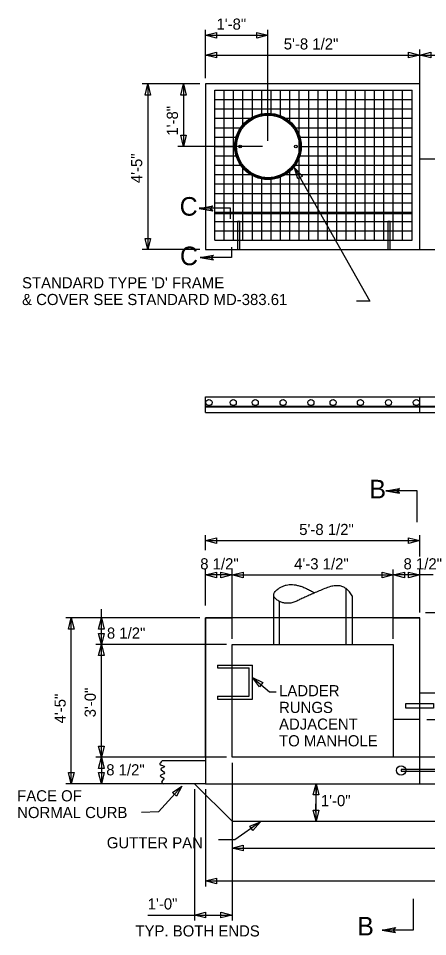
# Model space of a CAD drawing. Extents: x 100.2 to 136.1, y 126.8 to 178.4.
# Drawn here: x 101.15 to 112.05, y 153.91 to 178.38 of the extents above; entities that cross this region are included whole.
import ezdxf

# ---------------------------------------------------------------- set-up
doc = ezdxf.new("R2010")
doc.units = 0
for name, color, linetype in [('DETL-DIMS', 7, 'Continuous'), ('DETL-LINE', 7, 'Continuous'), ('DETL-NOTE', 7, 'Continuous')]:
    doc.layers.add(name, color=color, linetype=linetype)

msp = doc.modelspace()

# ---------------------------------------------------------------- linework, layer by layer
at = {"layer": 'DETL-DIMS'}
for p, q in [((106.133, 176.78), (106.133, 178.076)), ((106.133, 177.928), (107.799, 177.928)), ((107.799, 175.114), (107.799, 178.076)), ((106.133, 176.78), (106.133, 177.548)), ((111.841, 176.78), (111.841, 177.548)), ((111.841, 174.78), (111.841, 177.548)), ((106.133, 177.4), (111.841, 177.4)), ((111.841, 177.4), (116.841, 177.4)), ((105.985, 176.632), (104.451, 176.632)), ((104.599, 176.632), (104.599, 172.215)), ((105.985, 176.632), (105.402, 176.632)), ((105.55, 176.632), (105.55, 174.966)), ((107.651, 174.966), (105.402, 174.966)), ((105.968, 173.315), (106.326, 173.378)), ((105.968, 173.315), (106.326, 173.253)), ((106.258, 173.315), (106.326, 173.378)), ((106.326, 173.253), (106.258, 173.315)), ((105.985, 172.215), (104.451, 172.215)), ((105.994, 172.003), (106.352, 172.066)), ((106.284, 172.003), (106.352, 172.066)), ((105.994, 172.003), (106.352, 171.941)), ((106.352, 171.941), (106.284, 172.003)), ((110.939, 165.789), (111.297, 165.852)), ((110.939, 165.789), (111.297, 165.727)), ((111.229, 165.789), (111.297, 165.852)), ((111.297, 165.727), (111.229, 165.789)), ((106.133, 164.207), (106.133, 164.61)), ((106.133, 164.462), (111.841, 164.462)), ((111.841, 164.041), (111.841, 164.61)), ((106.133, 162.728), (106.133, 163.694)), ((106.841, 163.546), (106.133, 163.546)), ((106.781, 163.546), (106.841, 163.546)), ((106.841, 161.841), (106.841, 163.694)), ((106.841, 161.841), (106.841, 163.694)), ((106.841, 163.546), (111.133, 163.546)), ((111.133, 161.841), (111.133, 163.694)), ((111.133, 161.841), (111.133, 163.694)), ((111.841, 163.546), (111.133, 163.546)), ((111.841, 162.549), (111.841, 163.694)), ((112.193, 163.546), (111.841, 163.546)), ((103.362, 161.693), (103.362, 162.635)), ((111.989, 162.549), (113.451, 162.549)), ((105.985, 162.401), (102.413, 162.401)), ((102.561, 157.984), (102.561, 162.401)), ((105.985, 162.401), (103.214, 162.401)), ((106.693, 161.693), (103.214, 161.693)), ((106.693, 161.693), (103.214, 161.693)), ((103.362, 158.688), (103.362, 161.693)), ((111.989, 160.401), (113.451, 160.401)), ((106.693, 158.688), (103.214, 158.688)), ((106.693, 158.688), (103.214, 158.688)), ((103.362, 158.674), (103.362, 157.984)), ((106.841, 158.54), (106.841, 156.121)), ((104.865, 157.984), (102.413, 157.984)), ((105.985, 157.984), (103.214, 157.984)), ((105.841, 157.836), (105.841, 154.336)), ((106.133, 157.836), (106.133, 155.243)), ((109.078, 157.984), (109.077, 157.445)), ((109.078, 156.984), (109.078, 157.984)), ((109.078, 156.984), (109.077, 157.445)), ((106.841, 156.836), (106.841, 154.336)), ((106.841, 156.269), (126.841, 156.269)), ((106.133, 155.391), (127.549, 155.391)), ((104.597, 154.484), (105.841, 154.484)), ((105.841, 154.484), (106.841, 154.484)), ((110.837, 154.084), (111.195, 154.147)), ((110.837, 154.084), (111.195, 154.022)), ((111.127, 154.084), (111.195, 154.147)), ((111.195, 154.022), (111.127, 154.084))]:
    msp.add_line(p, q, dxfattribs=at)
for points in [[(106.43, 177.854), (106.133, 177.928), (106.43, 178.002)], [(107.502, 178.002), (107.799, 177.928), (107.502, 177.854)], [(106.43, 177.326), (106.133, 177.4), (106.43, 177.474)], [(111.544, 177.474), (111.841, 177.4), (111.544, 177.326)], [(112.138, 177.326), (111.841, 177.4), (112.138, 177.474)], [(104.525, 176.335), (104.599, 176.632), (104.673, 176.335)], [(105.476, 176.335), (105.55, 176.632), (105.624, 176.335)], [(105.624, 175.263), (105.55, 174.966), (105.476, 175.263)], [(108.59, 174.104), (108.509, 174.399), (108.719, 174.176)], [(106.326, 173.253), (105.968, 173.315), (106.326, 173.378), (106.258, 173.315)], [(104.673, 172.512), (104.599, 172.215), (104.525, 172.512)], [(106.352, 171.941), (105.994, 172.003), (106.352, 172.066), (106.284, 172.003)], [(111.297, 165.727), (110.939, 165.789), (111.297, 165.852), (111.229, 165.789)], [(106.43, 164.388), (106.133, 164.462), (106.43, 164.536)], [(111.544, 164.536), (111.841, 164.462), (111.544, 164.388)], [(106.43, 163.472), (106.133, 163.546), (106.43, 163.62)], [(106.544, 163.62), (106.841, 163.546), (106.544, 163.472)], [(107.138, 163.472), (106.841, 163.546), (107.138, 163.62)], [(110.836, 163.62), (111.133, 163.546), (110.836, 163.472)], [(111.43, 163.472), (111.133, 163.546), (111.43, 163.62)], [(111.544, 163.62), (111.841, 163.546), (111.544, 163.472)], [(102.487, 162.104), (102.561, 162.401), (102.635, 162.104)], [(103.288, 162.104), (103.362, 162.401), (103.436, 162.104)], [(103.436, 161.99), (103.362, 161.693), (103.288, 161.99)], [(103.288, 161.396), (103.362, 161.693), (103.436, 161.396)], [(107.569, 160.566), (107.39, 160.814), (107.664, 160.679)], [(103.436, 158.985), (103.362, 158.688), (103.288, 158.985)], [(103.288, 158.391), (103.362, 158.688), (103.436, 158.391)], [(102.635, 158.281), (102.561, 157.984), (102.487, 158.281)], [(103.436, 158.281), (103.362, 157.984), (103.288, 158.281)], [(105.253, 157.747), (105.508, 157.917), (105.363, 157.647)], [(109.003, 157.687), (109.078, 157.984), (109.151, 157.687)], [(109.151, 157.281), (109.078, 156.984), (109.003, 157.281)], [(107.312, 156.855), (107.598, 156.964), (107.397, 156.734)], [(107.138, 156.195), (106.841, 156.269), (107.138, 156.343)], [(106.43, 155.317), (106.133, 155.391), (106.43, 155.465)], [(106.138, 154.41), (105.841, 154.484), (106.138, 154.558)], [(106.544, 154.558), (106.841, 154.484), (106.544, 154.41)], [(111.195, 154.022), (110.837, 154.084), (111.195, 154.147), (111.127, 154.084)]]:
    msp.add_lwpolyline(points, close=True, dxfattribs=at)
for points in [[(108.509, 174.399), (110.512, 170.846), (110.151, 170.846)], [(106.8, 173.04), (106.8, 173.316), (105.968, 173.316)], [(106.826, 172.28), (106.826, 172.004), (105.993, 172.004)], [(111.772, 164.956), (111.772, 165.789), (110.939, 165.789)], [(107.39, 160.814), (107.84, 160.433), (108.02, 160.433)], [(105.508, 157.917), (104.887, 157.234), (104.432, 157.213)], [(107.598, 156.964), (106.915, 156.488), (106.48, 156.488)], [(110.837, 154.085), (111.671, 154.085), (111.671, 154.918)]]:
    msp.add_lwpolyline(points, dxfattribs=at)
at = {"layer": 'DETL-LINE'}
for p, q in [((106.383, 172.465), (106.383, 176.465)), ((106.383, 176.465), (111.633, 176.465)), ((106.633, 172.465), (106.633, 176.465)), ((106.883, 172.465), (106.883, 176.465)), ((107.133, 175.549), (107.133, 176.465)), ((107.383, 175.747), (107.383, 176.465)), ((107.633, 175.836), (107.633, 176.465)), ((107.883, 175.847), (107.883, 176.465)), ((108.133, 175.786), (108.133, 176.465)), ((108.383, 175.631), (108.383, 176.465)), ((108.633, 172.465), (108.633, 176.465)), ((108.883, 172.465), (108.883, 176.465)), ((109.133, 172.465), (109.133, 176.465)), ((109.383, 172.465), (109.383, 176.465)), ((109.633, 172.465), (109.633, 176.465)), ((109.883, 172.465), (109.883, 176.465)), ((110.133, 172.465), (110.133, 176.465)), ((110.383, 172.465), (110.383, 176.465)), ((110.633, 172.465), (110.633, 176.465)), ((110.883, 172.465), (110.883, 176.465)), ((111.133, 172.465), (111.133, 176.465)), ((111.383, 172.465), (111.383, 176.465)), ((111.633, 172.465), (111.633, 176.465)), ((106.383, 176.215), (111.633, 176.215)), ((106.383, 175.965), (111.633, 175.965)), ((106.383, 175.715), (107.328, 175.715)), ((108.27, 175.715), (111.633, 175.715)), ((106.383, 175.465), (107.068, 175.465)), ((108.53, 175.465), (111.633, 175.465)), ((106.383, 175.215), (106.95, 175.215)), ((108.648, 175.215), (111.633, 175.215)), ((106.383, 174.965), (106.914, 174.965)), ((108.684, 174.965), (111.633, 174.965)), ((106.383, 174.715), (106.95, 174.715)), ((108.648, 174.715), (111.633, 174.715)), ((111.841, 174.632), (127.549, 174.632)), ((111.841, 172.215), (111.841, 174.632)), ((106.383, 174.465), (107.069, 174.465)), ((107.133, 172.465), (107.133, 174.383)), ((108.383, 172.465), (108.383, 174.301)), ((108.529, 174.465), (111.633, 174.465)), ((106.383, 174.215), (107.331, 174.215)), ((107.383, 172.465), (107.383, 174.185)), ((107.633, 172.465), (107.633, 174.097)), ((107.883, 172.465), (107.883, 174.085)), ((108.133, 172.465), (108.133, 174.147)), ((108.267, 174.215), (111.633, 174.215)), ((106.383, 173.965), (111.633, 173.965)), ((106.383, 173.715), (111.633, 173.715)), ((106.383, 173.465), (111.633, 173.465)), ((106.383, 173.215), (111.633, 173.215)), ((106.383, 173.18), (111.633, 173.18)), ((106.383, 172.965), (111.633, 172.965)), ((106.383, 172.715), (111.633, 172.715)), ((106.383, 172.465), (111.633, 172.465)), ((111.841, 172.215), (127.549, 172.215)), ((106.133, 168.293), (127.549, 168.293)), ((106.133, 167.877), (106.133, 168.293)), ((111.841, 167.877), (111.841, 168.293)), ((106.133, 167.877), (127.549, 167.877)), ((107.949, 163.001), (107.949, 162.384)), ((109.875, 163.192), (109.875, 161.693)), ((110.037, 162.993), (110.037, 162.383)), ((108.095, 162.841), (108.095, 161.693)), ((106.133, 161.693), (106.133, 162.401)), ((106.133, 162.401), (106.841, 162.401)), ((107.949, 162.373), (107.949, 161.693)), ((110.037, 162.373), (110.037, 161.693)), ((111.133, 162.401), (111.841, 162.401)), ((106.133, 158.693), (106.133, 161.693)), ((108.046, 161.693), (108.046, 161.693)), ((106.459, 161.146), (106.83, 161.146)), ((106.459, 161.146), (106.459, 161.075)), ((106.459, 161.075), (106.829, 161.075)), ((106.834, 161.146), (107.39, 161.146)), ((106.834, 161.075), (107.294, 161.075)), ((107.294, 160.312), (107.294, 161.075)), ((107.39, 160.235), (107.39, 161.146)), ((106.459, 160.312), (106.829, 160.312)), ((106.459, 160.312), (106.459, 160.235)), ((106.834, 160.312), (107.294, 160.312)), ((111.841, 160.401), (127.549, 160.401)), ((111.841, 157.984), (111.841, 160.401)), ((106.459, 160.235), (106.83, 160.235)), ((106.836, 160.235), (107.39, 160.235)), ((111.841, 159.692), (111.133, 159.692)), ((112.031, 159.692), (126.841, 159.692)), ((106.135, 158.59), (104.985, 158.59)), ((126.841, 158.692), (111.133, 158.692)), ((106.133, 157.984), (105.013, 157.984)), ((105.841, 157.984), (106.841, 156.984)), ((106.133, 157.984), (106.841, 157.984)), ((111.133, 157.984), (111.841, 157.984)), ((111.841, 157.984), (127.549, 157.984)), ((106.841, 156.984), (126.805, 156.984))]:
    msp.add_line(p, q, dxfattribs=at)
for points in [[(106.133, 172.215), (111.841, 172.215), (111.841, 176.632), (106.133, 176.632)], [(106.986, 172.215), (107.051, 172.215), (107.051, 172.966), (106.986, 172.966)], [(110.988, 172.215), (111.053, 172.215), (111.053, 172.966), (110.988, 172.966)], [(127.549, 168.014), (106.133, 168.014), (106.133, 168.047), (127.549, 168.047)], [(106.133, 157.984), (111.841, 157.984), (111.841, 162.401), (106.133, 162.401)], [(106.841, 161.693), (111.133, 161.693), (111.133, 158.688), (106.841, 158.688)], [(111.472, 160.118), (112.208, 160.118), (112.208, 159.998), (111.472, 159.998)], [(111.341, 158.316), (112.344, 158.316), (112.344, 158.36), (111.341, 158.36)]]:
    msp.add_lwpolyline(points, close=True, dxfattribs=at)
for centre, radius in [((107.799, 174.966), 0.885), ((107.799, 174.966), 0.861), ((107.799, 174.966), 0.835), ((107.06, 174.966), 0.0366), ((108.538, 174.966), 0.0366), ((106.227, 168.141), 0.0814), ((106.873, 168.141), 0.0814), ((107.46, 168.141), 0.0814), ((108.201, 168.141), 0.0814), ((108.942, 168.141), 0.0814), ((109.533, 168.141), 0.0814), ((110.259, 168.141), 0.0814), ((111.007, 168.141), 0.0814), ((111.748, 168.141), 0.0814), ((111.341, 158.338), 0.125)]:
    msp.add_circle(centre, radius, dxfattribs=at)
msp.add_open_spline([(110.037, 162.993), (109.823, 163.394), (108.848, 162.991), (108.292, 162.716), (107.811, 163.033), (108.479, 163.412), (109.045, 163.066)], degree=2, dxfattribs=at)
msp.add_spline([(104.985, 158.59), (104.923, 158.502), (105.046, 158.435), (104.947, 158.378), (105.043, 158.272), (104.926, 158.191), (105.025, 158.113), (104.961, 158.022), (105.013, 157.984)], degree=3, dxfattribs=at)

# ---------------------------------------------------------------- texts
at = {"layer": 'DETL-NOTE'}
for s, height, p in [('1\'-8"', 0.297, (106.427, 178.076)), ('5\'-8 1/2"', 0.297, (108.219, 177.548)), ('C', 0.495, (105.448, 173.12)), ('C', 0.495, (105.456, 171.8)), ("STANDARD TYPE 'D' FRAME", 0.297, (101.251, 171.183)), ('& COVER SEE STANDARD MD-383.61', 0.297, (101.251, 170.738)), ('B', 0.495, (110.499, 165.587)), ('5\'-8 1/2"', 0.297, (108.63, 164.61)), ('8 1/2"', 0.297, (105.995, 163.694)), ('4\'-3 1/2"', 0.297, (108.495, 163.694)), ('8 1/2"', 0.297, (111.407, 163.694)), ('8 1/2"', 0.297, (103.51, 161.848)), ('LADDER', 0.297, (108.093, 160.313)), ('RUNGS', 0.297, (108.093, 159.868)), ('ADJACENT', 0.297, (108.093, 159.423)), ('TO MANHOLE', 0.297, (108.093, 158.978)), ('8 1/2"', 0.297, (103.492, 158.205)), ('FACE OF', 0.297, (101.121, 157.512)), ('1\'-0"', 0.297, (109.206, 157.384)), ('NORMAL CURB', 0.297, (101.121, 157.067)), ('GUTTER PAN', 0.297, (103.507, 156.261)), ('1\'-0"', 0.297, (104.597, 154.632)), ('B', 0.495, (110.176, 153.939)), ('TYP. BOTH ENDS', 0.297, (104.27, 153.912))]:
    msp.add_text(s, height=height, dxfattribs=at).set_placement(p)
for s, p in [('1\'-8"', (105.402, 175.253)), ('4\'-5"', (104.451, 173.987)), ('3\'-0"', (103.214, 159.752)), ('4\'-5"', (102.413, 159.59))]:
    msp.add_text(s, height=0.297, rotation=90, dxfattribs=at).set_placement(p)

doc.saveas('drawing.dxf')
